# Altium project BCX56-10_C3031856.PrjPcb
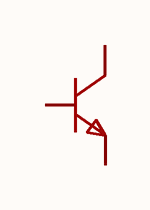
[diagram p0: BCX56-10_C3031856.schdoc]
1 sheet, 1 parts. Net scope: global (net labels, ports and power ports of the same name join across sheets).

## Sheet BCX56-10_C3031856.schdoc
size 127 x 101 mm

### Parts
Q?  bcx56-10  [SOT-89-3_L4.5-W2.5-P1.50-LS4.2-BR]  (value not drawn)

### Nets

Not connected (* = marked no-connect by the designer): Q? 1(B) 2(C) 3(E)

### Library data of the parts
Q? = bcx56-10: 晶体管类型:NPN;集电极电流(Ic):1A;集射极击穿电压(Vceo):80V;耗散功率(Pd):500mW;直流电流增益(hFE):100;; Manufacturer: CJ(江苏长电/长晶); Symbol: BCX56-10_C3031856; AddInBom: yes; ModelId: 6db690b7897d4d18a30d90c1b89525ee; ModelName: SOT-89-3_L4.3-W2.5-H1.6-LS4.1-P1.50; ModelTransform: 161.417,169.291,0,180,0,0,-18.661,0,0; type: NPN; Current - Collector(Ic): 1A; Collector - Emitter Voltage VCEO: 80V; Pd - Power Dissipation: 500mW; DC Current Gain: 100; Transition frequency(fT): 130MHz; Current - Collector Cutoff: 100nA; Vce Saturation(VCE(sat)): 500mV; Emitter-Base Voltage(Vebo): 5V; Number: 1个NPN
